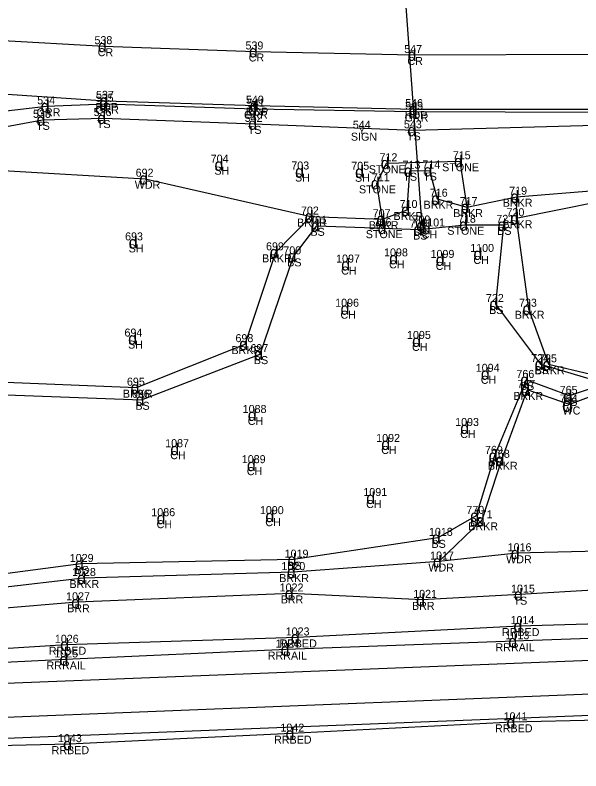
# Model space of a CAD drawing. Extents: x 17459 to 21139, y 33814 to 34251.
# Drawn here: x 17701.5 to 17842.8, y 33818.2 to 34007 of the extents above; entities that cross this region are included whole.
import ezdxf

# ---------------------------------------------------------------- set-up
doc = ezdxf.new("R2010")
doc.units = 0
for name, color, linetype in [('Level 11', 7, 'Continuous'), ('Level 12', 7, 'Continuous'), ('Level 14', 7, 'Continuous'), ('Level 16', 7, 'Continuous'), ('Level 17', 7, 'Continuous'), ('Level 38', 7, 'Continuous'), ('Level 43', 7, 'Continuous'), ('Level 46', 7, 'Continuous'), ('Level 47', 7, 'Continuous'), ('Level 48', 7, 'Continuous'), ('Level 58', 7, 'Continuous'), ('Level 59', 7, 'Continuous')]:
    doc.layers.add(name, color=color, linetype=linetype)

msp = doc.modelspace()

# ---------------------------------------------------------------- linework, layer by layer
at = {"layer": 'Level 11'}
for p, q in [((17682.21, 33988.51), (17724.06, 33985.61)), ((17724.06, 33985.61), (17761.6, 33984.41)), ((17761.6, 33984.41), (17801.33, 33983.54)), ((17801.33, 33983.54), (17846.67, 33983.55))]:
    msp.add_line(p, q, dxfattribs=at)
at = {"layer": 'Level 12'}
for p, q in [((17691.54, 33982.24), (17709.37, 33984.26)), ((17709.37, 33984.26), (17723.99, 33984.88)), ((17723.99, 33984.88), (17761.18, 33983.63)), ((17761.18, 33983.63), (17801.3, 33982.94)), ((17801.3, 33982.94), (17846.58, 33982.77)), ((17882.78, 33856.04), (17827.47, 33854.4)), ((17827.47, 33854.4), (17771.86, 33851.56)), ((17771.86, 33851.56), (17714.25, 33849.73)), ((17714.25, 33849.73), (17659.28, 33846.24)), ((17825.73, 33830.36), (17770.55, 33827.53)), ((17881.64, 33831.76), (17825.73, 33830.36)), ((17770.55, 33827.53), (17714.97, 33824.9)), ((17714.97, 33824.9), (17659.03, 33823.52))]:
    msp.add_line(p, q, dxfattribs=at)
at = {"layer": 'Level 14'}
for p, q in [((17696.62, 33968.31), (17734.01, 33966.16)), ((17734.01, 33966.16), (17775.34, 33956.7)), ((17826.72, 33961.66), (17869.67, 33965)), ((17877.65, 33873.91), (17826.8, 33872.59)), ((17826.8, 33872.59), (17807.38, 33870.53)), ((17770.35, 33862.54), (17717.01, 33860.34)), ((17803.14, 33860.95), (17770.35, 33862.54)), ((17717.01, 33860.34), (17660.99, 33855.69))]:
    msp.add_line(p, q, dxfattribs=at)
at = {"layer": 'Level 16'}
for p, q in [((17834.75, 33919.79), (17845.33, 33917.36)), ((17839.95, 33909.75), (17829.37, 33913.39)), ((17848.21, 33912.85), (17839.95, 33909.75))]:
    msp.add_line(p, q, dxfattribs=at)
at = {"layer": 'Level 17'}
for p, q in [((17806.94, 33961.16), (17814.34, 33959.07)), ((17814.34, 33959.07), (17826.72, 33961.66)), ((17826.72, 33961.66), (17826.7, 33956.28)), ((17766.59, 33947.77), (17775.34, 33956.7)), ((17775.34, 33956.7), (17793.26, 33956.05)), ((17793.26, 33956.05), (17799.43, 33958.35)), ((17826.7, 33956.28), (17829.73, 33933.67)), ((17758.95, 33924.83), (17766.59, 33947.77)), ((17829.73, 33933.67), (17834.75, 33919.79)), ((17731.83, 33913.96), (17758.95, 33924.83)), ((17685.75, 33915.89), (17731.83, 33913.96)), ((17829.37, 33913.39), (17823.02, 33895.94)), ((17823.02, 33895.94), (17818.11, 33880.82)), ((17818.11, 33880.82), (17807.38, 33870.53)), ((17807.38, 33870.53), (17770.89, 33867.89)), ((17718.48, 33866.41), (17661.56, 33859.74)), ((17770.89, 33867.89), (17718.48, 33866.41))]:
    msp.add_line(p, q, dxfattribs=at)
at = {"layer": 'Level 38'}
for p, q in [((17791.84, 33965), (17794.31, 33970.02)), ((17794.31, 33970.02), (17812.63, 33970.52)), ((17812.63, 33970.52), (17814.34, 33959.07)), ((17793.26, 33956.05), (17791.84, 33965)), ((17814.34, 33959.07), (17813.92, 33954.66)), ((17793.55, 33953.81), (17793.26, 33956.05))]:
    msp.add_line(p, q, dxfattribs=at)
at = {"layer": 'Level 48'}
for p, q in [((17682.87, 34001.61), (17723.67, 33999.27)), ((17723.67, 33999.27), (17761.41, 33997.95)), ((17761.41, 33997.95), (17801.05, 33997.07)), ((17801.05, 33997.07), (17847.25, 33997.27)), ((17708.32, 33980.87), (17723.52, 33981.31)), ((17723.52, 33981.31), (17761.22, 33979.86)), ((17692.7, 33978.03), (17708.32, 33980.87)), ((17761.22, 33979.86), (17800.98, 33978.26)), ((17800.98, 33978.26), (17846.31, 33979.57)), ((17799.43, 33958.35), (17800.08, 33968.15)), ((17800.08, 33968.15), (17805.02, 33968.21)), ((17805.02, 33968.21), (17806.94, 33961.16)), ((17826.7, 33956.28), (17869.67, 33965)), ((17771.02, 33946.76), (17776.83, 33954.39)), ((17776.83, 33954.39), (17793.55, 33953.81)), ((17793.55, 33953.81), (17802.48, 33953.45)), ((17802.48, 33953.45), (17813.92, 33954.66)), ((17813.92, 33954.66), (17823.5, 33954.63)), ((17823.5, 33954.63), (17821.47, 33934.86)), ((17762.69, 33922.34), (17771.02, 33946.76)), ((17821.47, 33934.86), (17832.78, 33919.86)), ((17733.1, 33910.93), (17762.69, 33922.34)), ((17832.78, 33919.86), (17845.62, 33916.02)), ((17829.19, 33915.89), (17821.29, 33896.92)), ((17839.95, 33911.9), (17829.19, 33915.89)), ((17847.65, 33914.51), (17839.95, 33911.9)), ((17685.19, 33912.67), (17733.1, 33910.93)), ((17821.29, 33896.92), (17816.68, 33881.93)), ((17816.68, 33881.93), (17807.07, 33876.44)), ((17807.07, 33876.44), (17771.04, 33871)), ((17717.92, 33869.91), (17662.7, 33862.75)), ((17771.04, 33871), (17717.92, 33869.91)), ((17879.32, 33865.36), (17827.6, 33862.25)), ((17827.6, 33862.25), (17803.14, 33860.95))]:
    msp.add_line(p, q, dxfattribs=at)
at = {"layer": 'Level 58'}
for p, q in [((18053.9, 33854.04), (17492.23, 33831.9)), ((17881.81, 33852.63), (17826.2, 33850.6)), ((17826.2, 33850.6), (17769.32, 33848.53)), ((17769.32, 33848.53), (17714.05, 33846.07)), ((18053.38, 33845.67), (17492.05, 33823.25)), ((17714.05, 33846.07), (17660.22, 33843.27)), ((18053.6, 33840.19), (17491.89, 33818.22))]:
    msp.add_line(p, q, dxfattribs=at)
at = {"layer": 'Level 59'}
msp.add_line((17803.22, 33954.48), (17797.22, 34035.65), dxfattribs=at)

# ---------------------------------------------------------------- texts
at = {"layer": 'Level 43'}
msp.add_text('Y', height=1.7, dxfattribs=at).set_placement((17787.36, 33977.31))
at = {"layer": 'Level 46'}
for s, p in [('538', (17721.31, 33999.77)), ('539', (17759.04, 33998.45)), ('CR', (17722.11, 33996.77)), ('547', (17798.69, 33997.57)), ('CR', (17759.84, 33995.45)), ('CR', (17799.49, 33994.57)), ('535', (17721.63, 33985.38)), ('537', (17721.7, 33986.11)), ('540', (17759.15, 33984.91)), ('534', (17707.01, 33984.76)), ('RDP', (17721.55, 33983.11)), ('541', (17759.39, 33984.13)), ('546', (17798.92, 33984.04)), ('545', (17798.94, 33983.44)), ('533', (17705.96, 33981.37)), ('GRR', (17706.86, 33981.76)), ('536', (17721.1, 33981.81)), ('GRR', (17721.48, 33982.38)), ('GRR', (17758.67, 33981.13)), ('RDP', (17759.08, 33981.91)), ('542', (17758.85, 33980.36)), ('GRR', (17798.79, 33980.44)), ('RDP', (17798.82, 33981.04)), ('TS', (17706.73, 33978.37)), ('TS', (17721.93, 33978.81)), ('TS', (17759.62, 33977.36)), ('544', (17785.85, 33978.66)), ('543', (17798.62, 33978.76)), ('SIGN', (17785.37, 33975.66)), ('TS', (17799.39, 33975.76)), ('704', (17750.35, 33970.17)), ('712', (17792.52, 33970.52)), ('715', (17810.83, 33971.02)), ('703', (17770.49, 33968.46)), ('705', (17785.47, 33968.39)), ('713', (17798.28, 33968.65)), ('714', (17803.23, 33968.71)), ('STONE', (17808.17, 33968.02)), ('692', (17731.6, 33966.66)), ('SH', (17751.28, 33967.17)), ('STONE', (17789.85, 33967.52)), ('SH', (17771.41, 33965.46)), ('SH', (17786.4, 33965.39)), ('711', (17790.62, 33965.5)), ('TS', (17798.49, 33965.65)), ('TS', (17803.43, 33965.71)), ('WDR', (17731.38, 33963.66)), ('STONE', (17787.39, 33962.5)), ('716', (17805.09, 33961.66)), ('719', (17824.92, 33962.16)), ('710', (17797.55, 33958.85)), ('BRKR', (17803.54, 33958.66)), ('717', (17812.54, 33959.57)), ('BRKR', (17823.31, 33959.16)), ('702', (17772.9, 33957.2)), ('707', (17790.82, 33956.55)), ('BRKR', (17810.93, 33956.57)), ('720', (17824.25, 33956.78)), ('701', (17774.96, 33954.89)), ('BRKR', (17796.02, 33955.85)), ('709', (17800.77, 33954.98)), ('718', (17812.13, 33955.16)), ('721', (17821.71, 33955.13)), ('BRKR', (17771.93, 33954.2)), ('BRKR', (17789.85, 33953.55)), ('706', (17791.05, 33954.31)), ('708', (17800.03, 33953.95)), ('1101', (17802.95, 33954.23)), ('BRKR', (17823.29, 33953.78)), ('BS', (17775.27, 33951.89)), ('STONE', (17789.09, 33951.31)), ('BS', (17800.92, 33950.95)), ('P', (17802.6, 33951.98)), ('CH', (17803.07, 33951.23)), ('STONE', (17809.46, 33952.16)), ('BS', (17821.94, 33952.13)), ('693', (17728.96, 33950.75)), ('SH', (17729.85, 33947.75)), ('699', (17764.17, 33948.27)), ('700', (17768.5, 33947.26)), ('1100', (17815.18, 33947.86)), ('BRKR', (17763.18, 33945.27)), ('1097', (17781.68, 33945.21)), ('1098', (17793.66, 33946.76)), ('1099', (17805.28, 33946.37)), ('BS', (17769.47, 33944.26)), ('CH', (17794.92, 33943.76)), ('CH', (17806.54, 33943.37)), ('CH', (17815.96, 33944.86)), ('CH', (17782.94, 33942.21)), ('1096', (17781.45, 33934.18)), ('722', (17819.11, 33935.36)), ('723', (17827.37, 33934.17)), ('BS', (17819.91, 33932.36)), ('CH', (17782.77, 33931.18)), ('BRKR', (17826.32, 33931.17)), ('694', (17728.81, 33926.72)), ('698', (17756.54, 33925.33)), ('1095', (17799.39, 33926.13)), ('SH', (17729.7, 33923.72)), ('697', (17760.28, 33922.84)), ('CH', (17800.65, 33923.13)), ('BRKR', (17755.54, 33922.33)), ('BS', (17761.13, 33919.84)), ('724', (17830.41, 33920.36)), ('725', (17832.38, 33920.29)), ('1094', (17816.57, 33917.92)), ('BS', (17831.22, 33917.36)), ('BRKR', (17831.34, 33917.29)), ('766', (17826.72, 33916.39)), ('695', (17729.42, 33914.46)), ('CH', (17817.83, 33914.92)), ('767', (17826.96, 33913.89)), ('BS', (17827.63, 33913.39)), ('BRKR', (17728.42, 33911.46)), ('696', (17730.64, 33911.43)), ('765', (17837.54, 33912.4)), ('BRKR', (17825.96, 33910.89)), ('764', (17837.54, 33910.25)), ('BS', (17838.39, 33909.4)), ('BS', (17731.54, 33908.43)), ('1088', (17758.34, 33907.64)), ('WC', (17838.25, 33907.25)), ('CH', (17759.6, 33904.64)), ('1093', (17811.42, 33904.38)), ('1092', (17791.69, 33900.39)), ('CH', (17812.68, 33901.38)), ('1087', (17738.98, 33899.09)), ('CH', (17792.95, 33897.39)), ('769', (17818.87, 33897.42)), ('768', (17820.61, 33896.44)), ('CH', (17740.24, 33896.09)), ('1089', (17758.12, 33895.1)), ('BS', (17819.73, 33894.42)), ('BRKR', (17819.61, 33893.44)), ('CH', (17759.38, 33892.1)), ('1091', (17788.49, 33886.89)), ('CH', (17789.18, 33883.89)), ('1086', (17735.52, 33881.85)), ('1090', (17762.64, 33882.36)), ('770', (17814.23, 33882.43)), ('771', (17816.31, 33881.32)), ('CH', (17763.98, 33879.36)), ('BS', (17815.12, 33879.43)), ('CH', (17736.83, 33878.85)), ('BRKR', (17814.7, 33878.32)), ('1018', (17804.87, 33876.94)), ('BS', (17805.51, 33873.94)), ('1016', (17824.54, 33873.09)), ('1029', (17715.14, 33870.41)), ('1019', (17768.83, 33871.5)), ('1017', (17805.17, 33871.03)), ('WDR', (17824.16, 33870.09)), ('1020', (17768.03, 33868.39)), ('BS', (17769.48, 33868.5)), ('WDR', (17804.74, 33868.03)), ('1028', (17715.71, 33866.91)), ('BS', (17716.36, 33867.41)), ('BRKR', (17767.48, 33865.39)), ('BRKR', (17715.07, 33863.91)), ('1022', (17767.58, 33863.04)), ('1015', (17825.39, 33862.75)), ('1027', (17714.23, 33860.84)), ('1021', (17800.94, 33861.45)), ('BRR', (17767.84, 33860.04)), ('BRR', (17800.63, 33858.45)), ('TS', (17826.01, 33859.75)), ('BRR', (17714.49, 33857.84)), ('1014', (17825.26, 33854.9)), ('1023', (17769.09, 33852.06)), ('RRBED', (17823.11, 33851.9)), ('1013', (17824, 33851.1)), ('1026', (17711.42, 33850.23)), ('1024', (17766.55, 33849.03)), ('RRBED', (17767.5, 33849.06)), ('RRBED', (17709.89, 33847.23)), ('RRRAIL', (17821.5, 33848.1)), ('1025', (17711.28, 33846.57)), ('RRRAIL', (17764.61, 33846.03)), ('RRRAIL', (17709.34, 33843.57)), ('1041', (17823.53, 33830.86)), ('1042', (17767.77, 33828.03)), ('RRBED', (17821.38, 33827.86)), ('1043', (17712.2, 33825.4)), ('RRBED', (17766.19, 33825.03)), ('RRBED', (17710.61, 33822.4))]:
    msp.add_text(s, height=2, dxfattribs=at).set_placement(p)
at = {"layer": 'Level 47'}
for height, p in [(3, (17722.17, 33997.77)), (3, (17759.91, 33996.45)), (3, (17799.55, 33995.57)), (3, (17722.56, 33984.11)), (3, (17707.87, 33982.76)), (3, (17722.49, 33983.38)), (3, (17759.68, 33982.13)), (3, (17760.1, 33982.91)), (3, (17799.83, 33982.04)), (3, (17799.8, 33981.44)), (3, (17706.82, 33979.37)), (3, (17722.02, 33979.81)), (3, (17759.72, 33978.36)), (3, (17799.48, 33976.76)), (3, (17811.13, 33969.02)), (3, (17751.29, 33968.17)), (3, (17792.81, 33968.52)), (3, (17771.43, 33966.46)), (3, (17786.41, 33966.39)), (3, (17798.58, 33966.65)), (3, (17803.52, 33966.71)), (3, (17732.51, 33964.66)), (3, (17790.34, 33963.5)), (3, (17805.44, 33959.66)), (3, (17825.22, 33960.16)), (3, (17812.84, 33957.57)), (3, (17797.93, 33956.85)), (3, (17773.84, 33955.2)), (3, (17791.76, 33954.55)), (3, (17825.2, 33954.78)), (3, (17775.33, 33952.89)), (3, (17792.05, 33952.31)), (3, (17800.98, 33951.95)), (3, (17801.72, 33952.98)), (3, (17803.09, 33952.23)), (3, (17812.42, 33953.16)), (3, (17822, 33953.13)), (3, (17729.86, 33948.75)), (3, (17765.09, 33946.27)), (3, (17769.52, 33945.26)), (3, (17794.93, 33944.76)), (3, (17806.56, 33944.37)), (3, (17815.98, 33945.86)), (3, (17782.95, 33943.21)), (3, (17819.97, 33933.36)), (3, (17782.78, 33932.18)), (3, (17828.23, 33932.17)), (3, (17729.72, 33924.72)), (3, (17757.45, 33923.33)), (3, (17800.66, 33924.13)), (3, (17761.19, 33920.84)), (3, (17831.28, 33918.36)), (3, (17833.25, 33918.29)), (3, (17817.84, 33915.92)), (3, (17827.69, 33914.39)), (3, (17730.33, 33912.46)), (3, (17827.87, 33911.89)), (3, (17838.45, 33910.4)), (3, (17731.6, 33909.43)), (3.7, (17838.1, 33907.9)), (3, (17759.61, 33905.64)), (3, (17812.69, 33902.38)), (3, (17740.26, 33897.09)), (3, (17792.96, 33898.39)), (3, (17819.79, 33895.42)), (3, (17759.4, 33893.1)), (3, (17821.52, 33894.44)), (3, (17789.2, 33884.89)), (3, (17764, 33880.36)), (3, (17815.18, 33880.43)), (3, (17736.84, 33879.85)), (3, (17816.61, 33879.32)), (3, (17805.57, 33874.94)), (3, (17825.3, 33871.09)), (3, (17769.54, 33869.5)), (3, (17805.88, 33869.03)), (3, (17716.42, 33868.41)), (3, (17716.98, 33864.91)), (3, (17769.39, 33866.39)), (3, (17768.85, 33861.04)), (3, (17801.64, 33859.45)), (3, (17826.1, 33860.75)), (3, (17715.51, 33858.84)), (3, (17825.97, 33852.9)), (3, (17770.36, 33850.06)), (3, (17712.75, 33848.23)), (3, (17824.7, 33849.1)), (3, (17767.82, 33847.03)), (3, (17712.55, 33844.57)), (3, (17824.23, 33828.86)), (3, (17769.05, 33826.03)), (3, (17713.47, 33823.4))]:
    msp.add_text('d', height=height, dxfattribs=at).set_placement(p)

doc.saveas('drawing.dxf')
